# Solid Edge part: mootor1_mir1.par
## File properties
Last saved by: Priit
Revision: 52
Accuracy: 0,990
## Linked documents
mootor1.par
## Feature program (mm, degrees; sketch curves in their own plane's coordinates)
part copy "CopiedPart_1"
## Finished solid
Body 1: solid body, 692 faces, 1912 edges, 1267 vertices, 2 separate solids.
  Faces by surface: spline 430, plane 204, cylinder 28, swept 16, cone 5, spun 4, sphere 3, torus 2
  Edges by curve: intersection 523, circle 494, spline 464, line 334, ellipse 49, curve on surface 48
Bounding box of the edges (mm; curved faces can reach further): 65.732 x 132.000 x 65.704, from (-32.3219, -132.0002, -30) to (33.4099, 0, 35.704).
Cylindrical faces by radius (mm): R1.0664 x5, R1.5 x16, R3.4731 x2, R4.1661 x3, R15 x1, R20 x1
Conical faces (half-angle, radius in mm at the cone's reference point): 10.7309 deg R23.0173 x1, 11.3099 deg R30 x1, 22.9214 deg R19.3065 x1, 38.6598 deg R20 x1, 45 deg R20 x1
Toroidal faces (ring radius, tube radius in mm): R16 r1 x1, R20 r5 x1
Spherical faces by radius (mm): R1 x1, R2.5 x1, R4 x1
Planar faces by outward normal: +x 5, +y 27, +z 7, -x 9, -y 29, -z 6, oblique 121
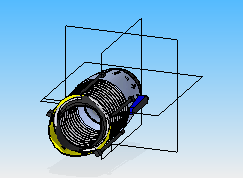
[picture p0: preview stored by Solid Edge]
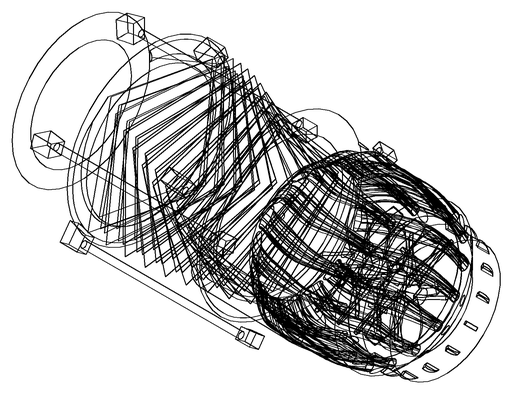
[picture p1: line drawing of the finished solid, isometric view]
